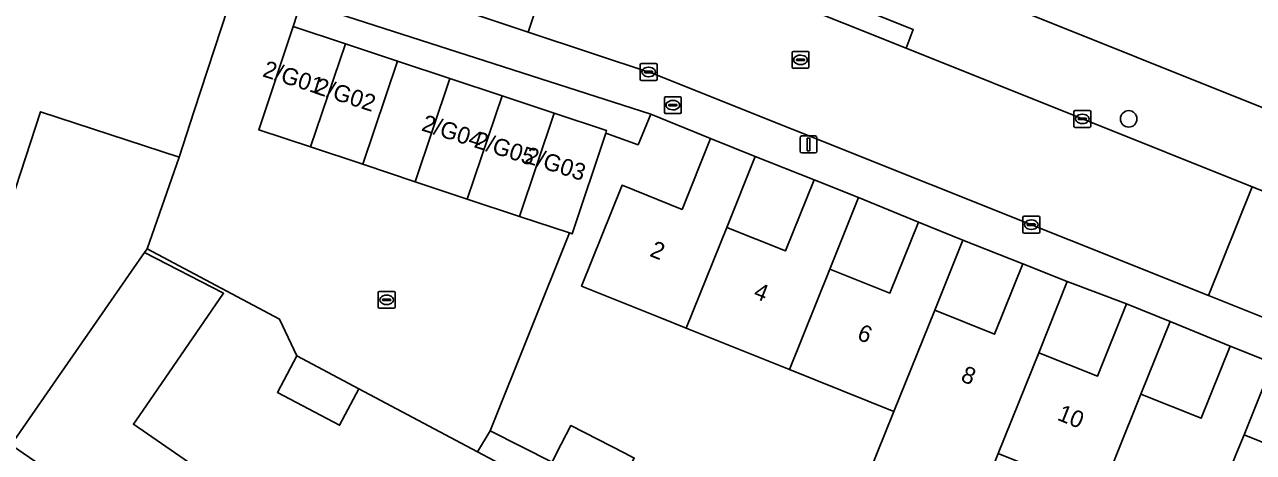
# Model space of a CAD drawing. Extents: x 162803 to 163818, y 381639 to 382475.
# Drawn here: x 163168.5 to 163241.2, y 382000 to 382025.4 of the extents above; entities that cross this region are included whole.
import ezdxf

# ---------------------------------------------------------------- set-up
doc = ezdxf.new("R2010")
doc.units = 0
for name, color, linetype in [('IMGEO_Boom', 7, 'Continuous'), ('IMGEO_Brandkraan', 7, 'Continuous'), ('IMGEO_Erf', 7, 'Continuous'), ('IMGEO_Kolk', 7, 'Continuous'), ('IMGEO_Lichtmast', 7, 'Continuous'), ('IMGEO_Muur', 7, 'Continuous'), ('IMGEO_Pand', 7, 'Continuous'), ('IMGEO_Pand_nummerreeks', 7, 'Continuous'), ('IMGEO_Rijbaan_lokaal_open', 7, 'Continuous'), ('IMGEO_Rioolput', 7, 'Continuous'), ('IMGEO_Voetpad_open', 7, 'Continuous')]:
    doc.layers.add(name, color=color, linetype=linetype)

msp = doc.modelspace()

# ---------------------------------------------------------------- linework, layer by layer
at = {"layer": 'IMGEO_Boom'}
msp.add_circle((163233.82, 382019.811), 0.489, dxfattribs=at)
at = {"layer": 'IMGEO_Brandkraan'}
for p, q in [((163206.329, 382020.2), (163206.329, 382021.052)), ((163206.404, 382021.126), (163207.256, 382021.126)), ((163206.631, 382020.669), (163207.029, 382020.669)), ((163206.817, 382020.906), (163206.842, 382020.906)), ((163207.33, 382021.052), (163207.33, 382020.2)), ((163207.256, 382020.126), (163206.404, 382020.126)), ((163206.588, 382020.62), (163206.588, 382020.632)), ((163207.026, 382020.583), (163206.628, 382020.583)), ((163206.84, 382020.346), (163206.815, 382020.346)), ((163207.072, 382020.632), (163207.072, 382020.62))]:
    msp.add_line(p, q, dxfattribs=at)
for points in [[(163206.329, 382020.2), (163206.329, 382021.052)], [(163206.404, 382021.126), (163207.256, 382021.126)], [(163207.33, 382021.052), (163207.33, 382020.2)], [(163207.256, 382020.126), (163206.404, 382020.126)]]:
    msp.add_lwpolyline(points, dxfattribs=at)
for centre, radius, start, end in [((163206.406, 382021.05), 0.0765, 91.55205, 178.44795), ((163206.406, 382021.05), 0.0765, 91.55205, 178.44795), ((163206.628, 382020.629), 0.0403, 85.87752, 175.75265), ((163207.033, 382020.631), 0.0386, 1.73085, 96.63898), ((163207.254, 382021.05), 0.0765, 1.55205, 88.44795), ((163207.254, 382021.05), 0.0765, 1.55205, 88.44795), ((163206.406, 382020.202), 0.0765, 181.55205, 268.44795), ((163206.406, 382020.202), 0.0765, 181.55205, 268.44795), ((163206.625, 382020.619), 0.0366, 178.93798, 274.71019), ((163207.029, 382020.626), 0.043, 264.86636, 352.45326), ((163207.254, 382020.202), 0.0765, 271.55205, 358.44795), ((163207.254, 382020.202), 0.0765, 271.55205, 358.44795)]:
    msp.add_arc(centre, radius, start, end, dxfattribs=at)
for centre, major_axis, ratio, start_param, end_param in [((163206.816, 382020.626), (-0.387, 0.002), 0.722429, 4.712389, 7.853982), ((163206.841, 382020.626), (-0.39, 0.002), 0.717154, 1.570796, 4.712389)]:
    msp.add_ellipse(centre, major_axis=major_axis, ratio=ratio, start_param=start_param, end_param=end_param, dxfattribs=at)
at = {"layer": 'IMGEO_Erf'}
for points in [[(163251.435, 382041.254), (163229.54, 382047.945), (163223.488, 382029.202), (163223.089, 382027.966), (163234.283, 382023.476), (163257.35, 382014.223)], [(163167.654, 382000.492), (163170.503, 382004.602), (163171.316, 382005.776), (163174.79, 382010.79), (163175.55, 382011.886), (163175.702, 382012.106), (163177.593, 382017.542), (163169.402, 382020.229), (163166.441, 382011.205)], [(163218.399, 381998.693), (163219.919, 382002.471), (163213.732, 382004.958), (163207.627, 382007.41), (163206.066, 382008.038), (163201.426, 382009.906), (163203.821, 382015.873), (163207.373, 382014.447), (163209.059, 382018.648), (163205.535, 382020.087), (163204.774, 382018.279), (163202.855, 382018.967), (163200.87, 382012.997), (163200.707, 382013.051), (163196.015, 382001.328), (163199.68, 381999.473)], [(163199.951, 382000), (163200.793, 382001.64), (163203.986, 382000)]]:
    msp.add_lwpolyline(points, dxfattribs=at)
for points in [[(163211.707, 382017.585), (163210.02, 382013.379), (163213.499, 382011.982), (163215.193, 382016.205)], [(163217.823, 382015.15), (163216.121, 382010.907), (163219.682, 382009.478), (163221.371, 382013.688)], [(163188.246, 382003.821), (163187.1, 382001.656), (163183.422, 382003.602), (163184.568, 382005.768), (163183.546, 382007.944), (163175.702, 382012.106), (163175.55, 382011.886), (163180.237, 382009.481), (163175.645, 382002.802), (163174.897, 382001.714), (163177.378, 382000), (163179.809, 381998.321), (163184.795, 381994.877), (163186.616, 381997.179), (163191.214, 381994.011), (163193.899, 381997.908), (163196.706, 381995.973), (163198.704, 381998.239), (163199.131, 381998.031), (163195.262, 382000.089)], [(163224.003, 382012.631), (163222.332, 382008.467), (163225.878, 382007.044), (163227.556, 382011.225)], [(163230.183, 382010.171), (163228.49, 382005.951), (163231.963, 382004.556), (163233.684, 382008.844)], [(163236.272, 382007.805), (163234.546, 382003.502), (163238.11, 382002.072), (163239.828, 382006.352)], [(163242.351, 382005.34), (163240.646, 382001.086), (163243.34, 382000), (163244.31, 381999.609), (163244.466, 382000), (163245.996, 382003.83)]]:
    msp.add_lwpolyline(points, close=True, dxfattribs=at)
at = {"layer": 'IMGEO_Kolk'}
for p, q in [((163204.894, 382022.163), (163204.894, 382023.015)), ((163204.969, 382023.089), (163205.821, 382023.089)), ((163205.382, 382022.869), (163205.407, 382022.869)), ((163205.895, 382023.015), (163205.895, 382022.163)), ((163205.153, 382022.583), (163205.153, 382022.595)), ((163205.591, 382022.546), (163205.193, 382022.546)), ((163205.196, 382022.632), (163205.594, 382022.632)), ((163205.405, 382022.309), (163205.38, 382022.309)), ((163205.637, 382022.595), (163205.637, 382022.583)), ((163205.821, 382022.089), (163204.969, 382022.089)), ((163230.573, 382019.383), (163230.573, 382020.235)), ((163230.648, 382020.309), (163231.5, 382020.309)), ((163231.061, 382020.089), (163231.086, 382020.089)), ((163231.574, 382020.235), (163231.574, 382019.383)), ((163231.5, 382019.309), (163230.648, 382019.309)), ((163230.832, 382019.803), (163230.832, 382019.815)), ((163231.27, 382019.766), (163230.872, 382019.766)), ((163230.875, 382019.852), (163231.273, 382019.852)), ((163231.084, 382019.529), (163231.059, 382019.529)), ((163231.316, 382019.815), (163231.316, 382019.803)), ((163227.551, 382013.114), (163227.551, 382013.966)), ((163227.626, 382014.04), (163228.478, 382014.04)), ((163227.81, 382013.534), (163227.81, 382013.546)), ((163228.248, 382013.497), (163227.85, 382013.497)), ((163227.853, 382013.583), (163228.251, 382013.583)), ((163228.039, 382013.82), (163228.064, 382013.82)), ((163228.294, 382013.546), (163228.294, 382013.534)), ((163228.552, 382013.966), (163228.552, 382013.114)), ((163228.478, 382013.04), (163227.626, 382013.04)), ((163228.062, 382013.26), (163228.037, 382013.26)), ((163189.384, 382008.662), (163189.384, 382009.514)), ((163189.459, 382009.588), (163190.311, 382009.588)), ((163189.643, 382009.082), (163189.643, 382009.094)), ((163190.081, 382009.045), (163189.683, 382009.045)), ((163189.686, 382009.131), (163190.084, 382009.131)), ((163189.872, 382009.368), (163189.897, 382009.368)), ((163190.127, 382009.094), (163190.127, 382009.082)), ((163190.385, 382009.514), (163190.385, 382008.662)), ((163190.311, 382008.588), (163189.459, 382008.588)), ((163189.895, 382008.808), (163189.87, 382008.808))]:
    msp.add_line(p, q, dxfattribs=at)
for points in [[(163204.894, 382022.163), (163204.894, 382023.015)], [(163204.969, 382023.089), (163205.821, 382023.089)], [(163205.895, 382023.015), (163205.895, 382022.163)], [(163205.821, 382022.089), (163204.969, 382022.089)], [(163230.573, 382019.383), (163230.573, 382020.235)], [(163230.648, 382020.309), (163231.5, 382020.309)], [(163231.574, 382020.235), (163231.574, 382019.383)], [(163231.5, 382019.309), (163230.648, 382019.309)], [(163227.551, 382013.114), (163227.551, 382013.966)], [(163227.626, 382014.04), (163228.478, 382014.04)], [(163228.552, 382013.966), (163228.552, 382013.114)], [(163228.478, 382013.04), (163227.626, 382013.04)], [(163189.384, 382008.662), (163189.384, 382009.514)], [(163189.459, 382009.588), (163190.311, 382009.588)], [(163190.385, 382009.514), (163190.385, 382008.662)], [(163190.311, 382008.588), (163189.459, 382008.588)]]:
    msp.add_lwpolyline(points, dxfattribs=at)
for centre, radius, start, end in [((163204.971, 382023.013), 0.0765, 91.55205, 178.44795), ((163204.971, 382023.013), 0.0765, 91.55205, 178.44795), ((163205.819, 382023.013), 0.0765, 1.55205, 88.44795), ((163205.819, 382023.013), 0.0765, 1.55205, 88.44795), ((163204.971, 382022.165), 0.0765, 181.55205, 268.44795), ((163204.971, 382022.165), 0.0765, 181.55205, 268.44795), ((163205.193, 382022.592), 0.0403, 85.87752, 175.75265), ((163205.19, 382022.582), 0.0366, 178.93798, 274.71019), ((163205.594, 382022.589), 0.043, 264.86636, 352.45326), ((163205.598, 382022.594), 0.0386, 1.73085, 96.63898), ((163205.819, 382022.165), 0.0765, 271.55205, 358.44795), ((163205.819, 382022.165), 0.0765, 271.55205, 358.44795), ((163230.65, 382020.233), 0.0765, 91.55205, 178.44795), ((163230.65, 382020.233), 0.0765, 91.55205, 178.44795), ((163231.498, 382020.233), 0.0765, 1.55205, 88.44795), ((163231.498, 382020.233), 0.0765, 1.55205, 88.44795), ((163230.65, 382019.385), 0.0765, 181.55205, 268.44795), ((163230.65, 382019.385), 0.0765, 181.55205, 268.44795), ((163230.872, 382019.812), 0.0403, 85.87752, 175.75265), ((163230.869, 382019.802), 0.0366, 178.93798, 274.71019), ((163231.273, 382019.809), 0.043, 264.86636, 352.45326), ((163231.277, 382019.814), 0.0386, 1.73085, 96.63898), ((163231.498, 382019.385), 0.0765, 271.55205, 358.44795), ((163231.498, 382019.385), 0.0765, 271.55205, 358.44795), ((163227.628, 382013.964), 0.0765, 91.55205, 178.44795), ((163227.628, 382013.964), 0.0765, 91.55205, 178.44795), ((163227.85, 382013.543), 0.0403, 85.87752, 175.75265), ((163227.847, 382013.533), 0.0366, 178.93798, 274.71019), ((163228.251, 382013.54), 0.043, 264.86636, 352.45326), ((163228.255, 382013.545), 0.0386, 1.73085, 96.63898), ((163228.476, 382013.964), 0.0765, 1.55205, 88.44795), ((163228.476, 382013.964), 0.0765, 1.55205, 88.44795), ((163227.628, 382013.116), 0.0765, 181.55205, 268.44795), ((163227.628, 382013.116), 0.0765, 181.55205, 268.44795), ((163228.476, 382013.116), 0.0765, 271.55205, 358.44795), ((163228.476, 382013.116), 0.0765, 271.55205, 358.44795), ((163189.461, 382009.512), 0.0765, 91.55205, 178.44795), ((163189.461, 382009.512), 0.0765, 91.55205, 178.44795), ((163189.683, 382009.091), 0.0403, 85.87752, 175.75265), ((163189.68, 382009.081), 0.0366, 178.93798, 274.71019), ((163190.084, 382009.088), 0.043, 264.86636, 352.45326), ((163190.088, 382009.093), 0.0386, 1.73085, 96.63898), ((163190.309, 382009.512), 0.0765, 1.55205, 88.44795), ((163190.309, 382009.512), 0.0765, 1.55205, 88.44795), ((163189.461, 382008.664), 0.0765, 181.55205, 268.44795), ((163189.461, 382008.664), 0.0765, 181.55205, 268.44795), ((163190.309, 382008.664), 0.0765, 271.55205, 358.44795), ((163190.309, 382008.664), 0.0765, 271.55205, 358.44795)]:
    msp.add_arc(centre, radius, start, end, dxfattribs=at)
for centre, major_axis, ratio, start_param, end_param in [((163205.381, 382022.589), (-0.387, 0.002), 0.722429, 4.712389, 7.853982), ((163205.406, 382022.589), (-0.39, 0.002), 0.717154, 1.570796, 4.712389), ((163231.06, 382019.809), (-0.387, 0.002), 0.722429, 4.712389, 7.853982), ((163231.085, 382019.809), (-0.39, 0.002), 0.717154, 1.570796, 4.712389), ((163228.038, 382013.54), (-0.387, 0.002), 0.722429, 4.712389, 7.853982), ((163228.063, 382013.54), (-0.39, 0.002), 0.717154, 1.570796, 4.712389), ((163189.871, 382009.088), (-0.387, 0.002), 0.722429, 4.712389, 7.853982), ((163189.896, 382009.088), (-0.39, 0.002), 0.717154, 1.570796, 4.712389)]:
    msp.add_ellipse(centre, major_axis=major_axis, ratio=ratio, start_param=start_param, end_param=end_param, dxfattribs=at)
at = {"layer": 'IMGEO_Lichtmast'}
for p, q in [((163214.366, 382017.896), (163214.366, 382018.696)), ((163214.366, 382018.696), (163214.366, 382017.896)), ((163214.466, 382018.796), (163215.256, 382018.796)), ((163215.256, 382018.796), (163214.466, 382018.796)), ((163215.356, 382018.696), (163215.356, 382017.896)), ((163215.356, 382017.896), (163215.356, 382018.696)), ((163215.256, 382017.796), (163214.466, 382017.796)), ((163214.466, 382017.796), (163215.256, 382017.796))]:
    msp.add_line(p, q, dxfattribs=at)
msp.add_lwpolyline([(163214.786, 382018.671), (163214.936, 382018.671), (163214.936, 382017.921), (163214.786, 382017.921), (163214.786, 382018.671)], dxfattribs=at)
for centre, start, end in [((163214.466, 382018.696), 90, 180), ((163214.466, 382018.696), 90, 180), ((163215.256, 382018.696), 0, 90), ((163215.256, 382018.696), 360, 90), ((163214.466, 382017.896), 180, 270), ((163214.466, 382017.896), 180, 270), ((163215.256, 382017.896), 270, 0), ((163215.256, 382017.896), 270, 0)]:
    msp.add_arc(centre, 0.1, start, end, dxfattribs=at)
at = {"layer": 'IMGEO_Muur'}
msp.add_lwpolyline([(163200.707, 382013.051), (163196.015, 382001.328)], dxfattribs=at)
at = {"layer": 'IMGEO_Pand'}
for points in [[(163180.491, 382026.378), (163163.058, 382032.097), (163161.135, 382026.232), (163159.709, 382026.7), (163158.7, 382023.623), (163158.916, 382023.552), (163156.254, 382015.436), (163159.522, 382014.364), (163158.189, 382010.298), (163161.724, 382007.587), (163164.916, 382011.705), (163166.441, 382011.205), (163169.402, 382020.229), (163177.593, 382017.542), (163178.496, 382020.295)], [(163185.384, 382018.146), (163187.442, 382024.256), (163184.35, 382025.284), (163182.315, 382019.166)], [(163185.384, 382018.146), (163188.476, 382017.118), (163190.535, 382023.228), (163187.442, 382024.256)], [(163191.569, 382016.089), (163193.627, 382022.199), (163190.535, 382023.228), (163188.476, 382017.118)], [(163196.72, 382021.171), (163193.627, 382022.199), (163191.569, 382016.089), (163194.661, 382015.061)], [(163196.72, 382021.171), (163194.661, 382015.061), (163197.753, 382014.033), (163199.812, 382020.143)], [(163197.753, 382014.033), (163200.707, 382013.051), (163200.87, 382012.997), (163202.855, 382018.967), (163202.904, 382019.115), (163199.812, 382020.143)], [(163210.02, 382013.379), (163211.707, 382017.585), (163209.059, 382018.648), (163207.373, 382014.447), (163203.821, 382015.873), (163201.426, 382009.906), (163206.066, 382008.038), (163207.627, 382007.41)], [(163213.732, 382004.958), (163216.121, 382010.907), (163217.823, 382015.15), (163215.193, 382016.205), (163213.499, 382011.982), (163210.02, 382013.379), (163207.627, 382007.41)], [(163219.919, 382002.471), (163222.332, 382008.467), (163224.003, 382012.631), (163221.371, 382013.688), (163219.682, 382009.478), (163216.121, 382010.907), (163213.732, 382004.958)], [(163174.897, 382001.714), (163175.645, 382002.802), (163180.237, 382009.481), (163175.55, 382011.886), (163174.79, 382010.79), (163171.316, 382005.776), (163170.503, 382004.602), (163167.654, 382000.492), (163168.37, 382000), (163171.797, 381997.646), (163170.009, 381995.052), (163175.126, 381991.526), (163179.809, 381998.321), (163177.378, 382000)], [(163228.49, 382005.951), (163230.183, 382010.171), (163227.556, 382011.225), (163225.878, 382007.044), (163222.332, 382008.467), (163219.919, 382002.471), (163218.399, 381998.693), (163222.224, 381997.154), (163223.305, 381998.262), (163225.114, 381997.535), (163226.096, 381999.982)], [(163234.546, 382003.502), (163236.272, 382007.805), (163233.684, 382008.844), (163231.963, 382004.556), (163228.49, 382005.951), (163226.096, 381999.982), (163232.158, 381997.544), (163233.142, 382000)], [(163240.21, 382000), (163240.646, 382001.086), (163242.351, 382005.34), (163239.828, 382006.352), (163238.11, 382002.072), (163234.546, 382003.502), (163233.142, 382000), (163232.158, 381997.544), (163230.613, 381993.688), (163236.695, 381991.242), (163238.245, 381995.096)], [(163184.568, 382005.768), (163183.422, 382003.602), (163187.1, 382001.656), (163188.246, 382003.821)], [(163238.245, 381995.096), (163244.64, 381992.524), (163243.166, 381988.91), (163245.563, 381987.926), (163246.799, 381990.977), (163248.676, 381995.611), (163246.315, 381996.568), (163247.689, 382000), (163248.776, 382002.714), (163245.996, 382003.83), (163244.466, 382000), (163244.31, 381999.609), (163243.34, 382000), (163240.646, 382001.086), (163240.21, 382000)], [(163203.432, 381997.546), (163204.545, 381999.713), (163203.986, 382000), (163200.793, 382001.64), (163199.951, 382000), (163199.68, 381999.473)]]:
    msp.add_lwpolyline(points, close=True, dxfattribs=at)
at = {"layer": 'IMGEO_Rijbaan_lokaal_open'}
for points in [[(163198.267, 382024.955), (163200.444, 382031.53), (163197.135, 382032.623), (163194.957, 382026.049)], [(163198.267, 382024.955), (163205.64, 382022.508), (163238.551, 382009.339), (163241.137, 382015.775), (163220.636, 382023.993), (163209.414, 382028.496), (163208.637, 382028.823), (163200.444, 382031.53)], [(163194.661, 382015.061), (163191.569, 382016.089), (163188.476, 382017.118), (163185.384, 382018.146), (163182.315, 382019.166), (163184.35, 382025.284), (163184.822, 382026.746), (163181.042, 382027.961), (163180.491, 382026.378), (163178.496, 382020.295), (163177.593, 382017.542), (163175.702, 382012.106), (163183.546, 382007.944), (163184.568, 382005.768), (163188.246, 382003.821), (163195.262, 382000.089), (163196.015, 382001.328), (163200.707, 382013.051), (163197.753, 382014.033)], [(163244.386, 382014.495), (163241.137, 382015.775), (163238.551, 382009.339), (163241.791, 382008.043)]]:
    msp.add_lwpolyline(points, close=True, dxfattribs=at)
at = {"layer": 'IMGEO_Rioolput'}
for p, q in [((163213.89, 382022.88), (163213.89, 382023.732)), ((163213.965, 382023.806), (163214.817, 382023.806)), ((163214.378, 382023.586), (163214.403, 382023.586)), ((163214.891, 382023.732), (163214.891, 382022.88)), ((163214.149, 382023.3), (163214.149, 382023.312)), ((163214.587, 382023.263), (163214.189, 382023.263)), ((163214.192, 382023.349), (163214.59, 382023.349)), ((163214.401, 382023.026), (163214.376, 382023.026)), ((163214.633, 382023.312), (163214.633, 382023.3)), ((163214.817, 382022.806), (163213.965, 382022.806))]:
    msp.add_line(p, q, dxfattribs=at)
for points in [[(163213.89, 382022.88), (163213.89, 382023.732)], [(163213.965, 382023.806), (163214.817, 382023.806)], [(163214.891, 382023.732), (163214.891, 382022.88)], [(163214.817, 382022.806), (163213.965, 382022.806)]]:
    msp.add_lwpolyline(points, dxfattribs=at)
for centre, radius, start, end in [((163213.967, 382023.73), 0.0765, 91.55205, 178.44795), ((163213.967, 382023.73), 0.0765, 91.55205, 178.44795), ((163214.815, 382023.73), 0.0765, 1.55205, 88.44795), ((163214.815, 382023.73), 0.0765, 1.55205, 88.44795), ((163213.967, 382022.882), 0.0765, 181.55205, 268.44795), ((163213.967, 382022.882), 0.0765, 181.55205, 268.44795), ((163214.189, 382023.309), 0.0403, 85.87752, 175.75265), ((163214.186, 382023.299), 0.0366, 178.93798, 274.71019), ((163214.59, 382023.306), 0.043, 264.86636, 352.45326), ((163214.594, 382023.311), 0.0386, 1.73085, 96.63898), ((163214.815, 382022.882), 0.0765, 271.55205, 358.44795), ((163214.815, 382022.882), 0.0765, 271.55205, 358.44795)]:
    msp.add_arc(centre, radius, start, end, dxfattribs=at)
for centre, major_axis, ratio, start_param, end_param in [((163214.377, 382023.306), (-0.387, 0.002), 0.722429, 4.712389, 7.853982), ((163214.402, 382023.306), (-0.39, 0.002), 0.717154, 1.570796, 4.712389)]:
    msp.add_ellipse(centre, major_axis=major_axis, ratio=ratio, start_param=start_param, end_param=end_param, dxfattribs=at)
at = {"layer": 'IMGEO_Voetpad_open'}
for points in [[(163161.734, 382044.254), (163197.135, 382032.623), (163200.444, 382031.53), (163208.637, 382028.823), (163209.414, 382028.496), (163209.865, 382029.593), (163221.055, 382025.109), (163220.636, 382023.993), (163241.137, 382015.775), (163244.386, 382014.495), (163257.778, 382009.046), (163258.164, 382010.136), (163269.369, 382005.691), (163268.89, 382004.622), (163276.65, 382001.485), (163297.139, 381992.593), (163300.295, 381991.223), (163309.414, 381987.243), (163309.902, 381988.367), (163319.822, 381984.046), (163319.351, 381982.939), (163334.063, 381976.602), (163337.225, 381975.21), (163360.196, 381965.225)], [(163205.64, 382022.508), (163198.267, 382024.955), (163194.957, 382026.049), (163186.097, 382029.003), (163185.727, 382027.896), (163176.126, 382031.046), (163176.484, 382032.15), (163160.645, 382037.327)], [(163158.644, 382035.308), (163181.042, 382027.961), (163184.822, 382026.746), (163205.535, 382020.087), (163209.059, 382018.648), (163211.707, 382017.585), (163215.193, 382016.205), (163217.823, 382015.15), (163221.371, 382013.688), (163224.003, 382012.631), (163227.556, 382011.225), (163230.183, 382010.171), (163233.684, 382008.844), (163236.272, 382007.805), (163239.828, 382006.352), (163242.351, 382005.34), (163245.996, 382003.83), (163248.776, 382002.714), (163255.605, 382000), (163270.341, 381994.144), (163272.574, 381993.14)], [(163361.532, 381969.699), (163322.499, 381986.595), (163317.691, 381988.56), (163314.664, 381989.892), (163311.571, 381991.346), (163291.511, 382000), (163271.449, 382008.655), (163266.604, 382010.447), (163263.485, 382011.703), (163260.414, 382012.994), (163257.35, 382014.223), (163234.283, 382023.476), (163223.089, 382027.966)], [(163269.305, 381997.039), (163241.791, 382008.043), (163238.551, 382009.339), (163205.64, 382022.508)], [(163199.68, 381999.473), (163196.015, 382001.328), (163195.262, 382000.089), (163199.131, 381998.031)]]:
    msp.add_lwpolyline(points, dxfattribs=at)
for points in [[(163221.055, 382025.109), (163209.865, 382029.593), (163209.414, 382028.496), (163220.636, 382023.993)], [(163184.35, 382025.284), (163187.442, 382024.256), (163190.535, 382023.228), (163193.627, 382022.199), (163196.72, 382021.171), (163199.812, 382020.143), (163202.904, 382019.115), (163202.855, 382018.967), (163204.774, 382018.279), (163205.535, 382020.087), (163184.822, 382026.746)]]:
    msp.add_lwpolyline(points, close=True, dxfattribs=at)

# ---------------------------------------------------------------- texts
at = {"layer": 'IMGEO_Pand_nummerreeks'}
for s, rotation, p in [('2/G01', 342.17456, (163182.487, 382022.341)), ('2/G02', 342.17456, (163185.563, 382021.332)), ('2/G04', 342.17456, (163191.893, 382019.137)), ('2/G05', 342.17456, (163195.004, 382018.142)), ('2/G03', 342.17456, (163198.004, 382017.235)), ('2', 338.08031, (163205.406, 382011.699)), ('4', 338.08031, (163211.544, 382009.229)), ('6', 338.08031, (163217.679, 382006.76)), ('8', 338.07863, (163223.819, 382004.29)), ('10', 338.07863, (163229.528, 382001.992))]:
    msp.add_text(s, height=1, rotation=rotation, dxfattribs=at).set_placement(p)

doc.saveas('drawing.dxf')
